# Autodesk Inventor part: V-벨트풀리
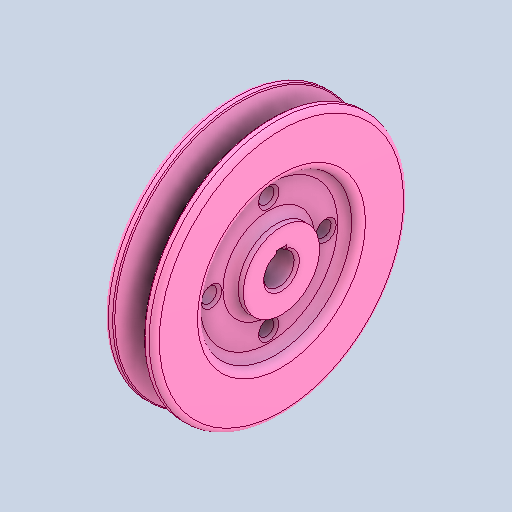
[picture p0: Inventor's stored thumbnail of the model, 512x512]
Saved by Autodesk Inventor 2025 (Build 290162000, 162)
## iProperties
Created: 2024-07
Part Number: V-벨트풀리
Material: 강철, 연강
Document SubType Name: Modeling
Designer: anfro
Density: 7.86 g/cm^3
Appearance: 기본값
Author: jhkim
Sending System: Autodesk Inventor 2025
Preprocessor: ST-DEVELOPER v20
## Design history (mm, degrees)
feature "솔리드1"
node "솔리드2"
